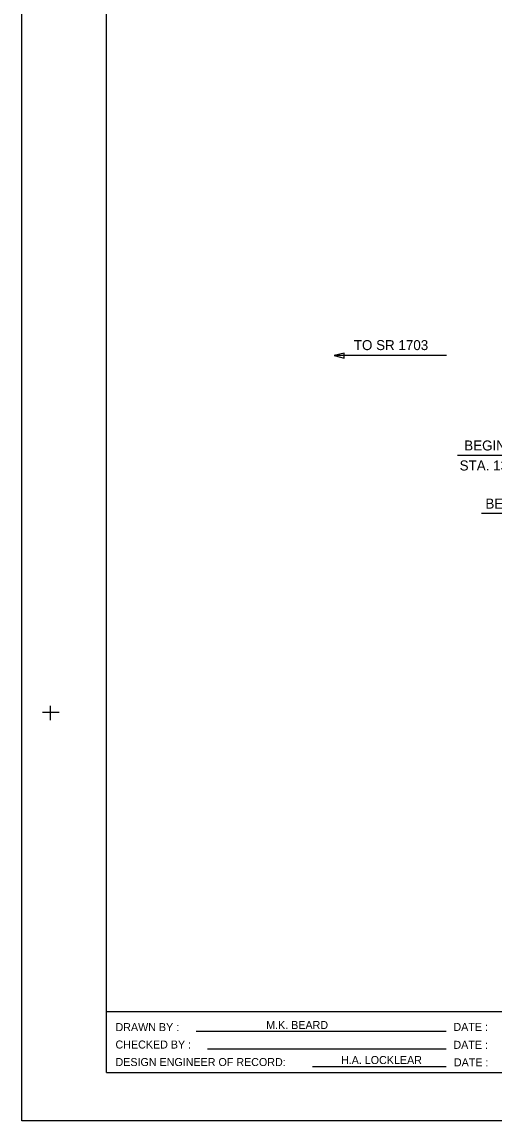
# Model space of a CAD drawing. Extents: x -20 to 509, y -659 to 21.
# Drawn here: x 0 to 47.1, y -176.3 to -66.5 of the extents above; entities that cross this region are included whole.
import ezdxf

# ---------------------------------------------------------------- set-up
doc = ezdxf.new("R2010")
doc.units = 0
for name, color, linetype in [('Arrowhead Terminators CELL', 7, 'Continuous'), ('Dimension Lines', 7, 'Continuous'), ('Plan Sheet CELL', 7, 'Continuous'), ('Plot Shape CELL', 7, 'Continuous'), ('Subtitle Text', 7, 'Continuous'), ('Text', 7, 'Continuous')]:
    doc.layers.add(name, color=color, linetype=linetype)

msp = doc.modelspace()

# ---------------------------------------------------------------- linework, layer by layer
at = {"layer": 'Arrowhead Terminators CELL'}
msp.add_lwpolyline([(31.19, -99.82), (32.19, -100.07), (32.19, -99.57)], close=True, dxfattribs=at)
at = {"layer": 'Dimension Lines'}
for p, q in [((42.39, -99.82), (31.19, -99.82)), ((58.73, -109.8), (43.49, -109.8)), ((64.29, -115.61), (45.91, -115.61))]:
    msp.add_line(p, q, dxfattribs=at)
at = {"layer": 'Plan Sheet CELL'}
for p, q in [((8.43, -171.45), (8.43, -3.45)), ((2.86, -136.25), (2.86, -134.8)), ((2.04, -135.45), (3.72, -135.45)), ((8.43, -165.36), (54.62, -165.36)), ((17.38, -167.34), (42.36, -167.34)), ((18.52, -169.09), (42.36, -169.09)), ((29.01, -170.85), (42.36, -170.85)), ((29.01, -170.85), (42.36, -170.85)), ((8.43, -171.45), (264.43, -171.45)), ((0, -176.3), (0, -176.3))]:
    msp.add_line(p, q, dxfattribs=at)
at = {"layer": 'Plot Shape CELL'}
msp.add_lwpolyline([(0, -0.3), (264.5, -0.3), (264.5, -176.3), (0, -176.3)], close=True, dxfattribs=at)

# ---------------------------------------------------------------- texts
at = {"layer": 'Plan Sheet CELL'}
for s, p in [('DRAWN BY :', (9.34, -167.32)), ('DATE :', (43.09, -167.3)), ('CHECKED BY :', (9.34, -169.06)), ('DATE :', (43.09, -169.09)), ('DESIGN ENGINEER OF RECORD:', (9.34, -170.81)), ('DATE :', (43.14, -170.84))]:
    msp.add_text(s, height=0.8, dxfattribs=at).set_placement(p)
at = {"layer": 'Subtitle Text'}
for s, p in [('M.K. BEARD', (24.39, -167.11)), ('H.A. LOCKLEAR', (31.86, -170.61))]:
    msp.add_text(s, height=0.8, dxfattribs=at).set_placement(p)
at = {"layer": 'Text'}
for s, p in [('TO SR 1703', (33.14, -99.27)), ('BEGIN APP. SLAB', (44.17, -109.3)), ('STA. 13+69.00 -L-', (43.71, -111.3)), ('BEGIN FRONT SLOPE', (46.29, -115.11))]:
    msp.add_text(s, height=1, dxfattribs=at).set_placement(p)

doc.saveas('drawing.dxf')
